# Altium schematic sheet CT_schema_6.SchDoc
size 612 x 325 mm
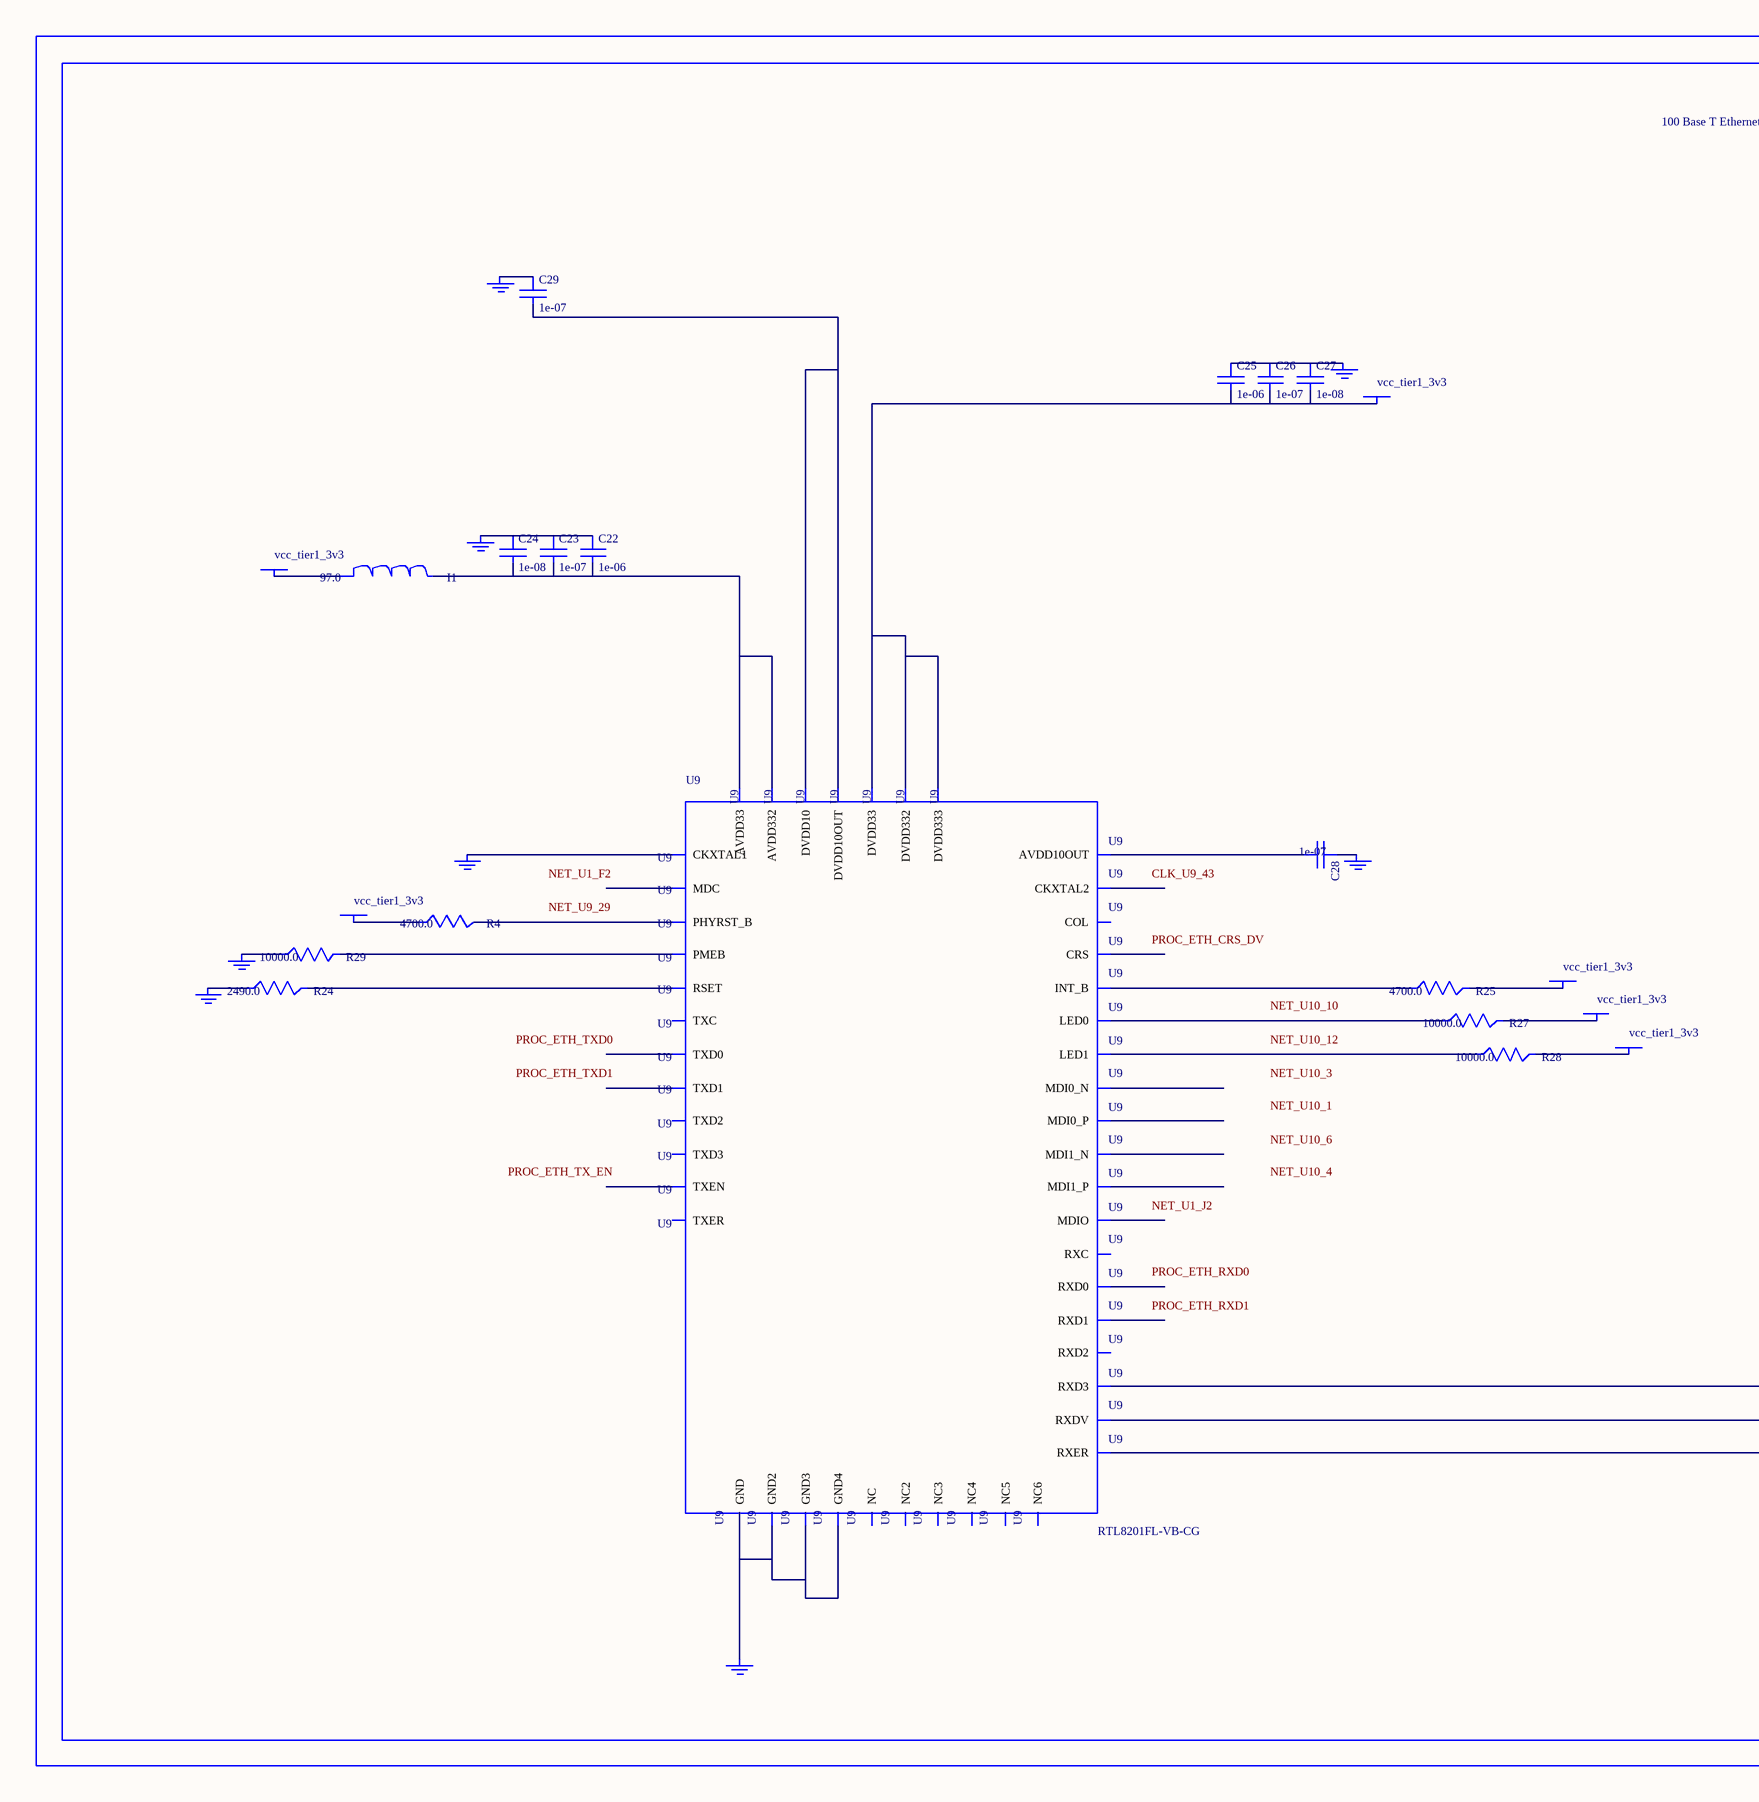
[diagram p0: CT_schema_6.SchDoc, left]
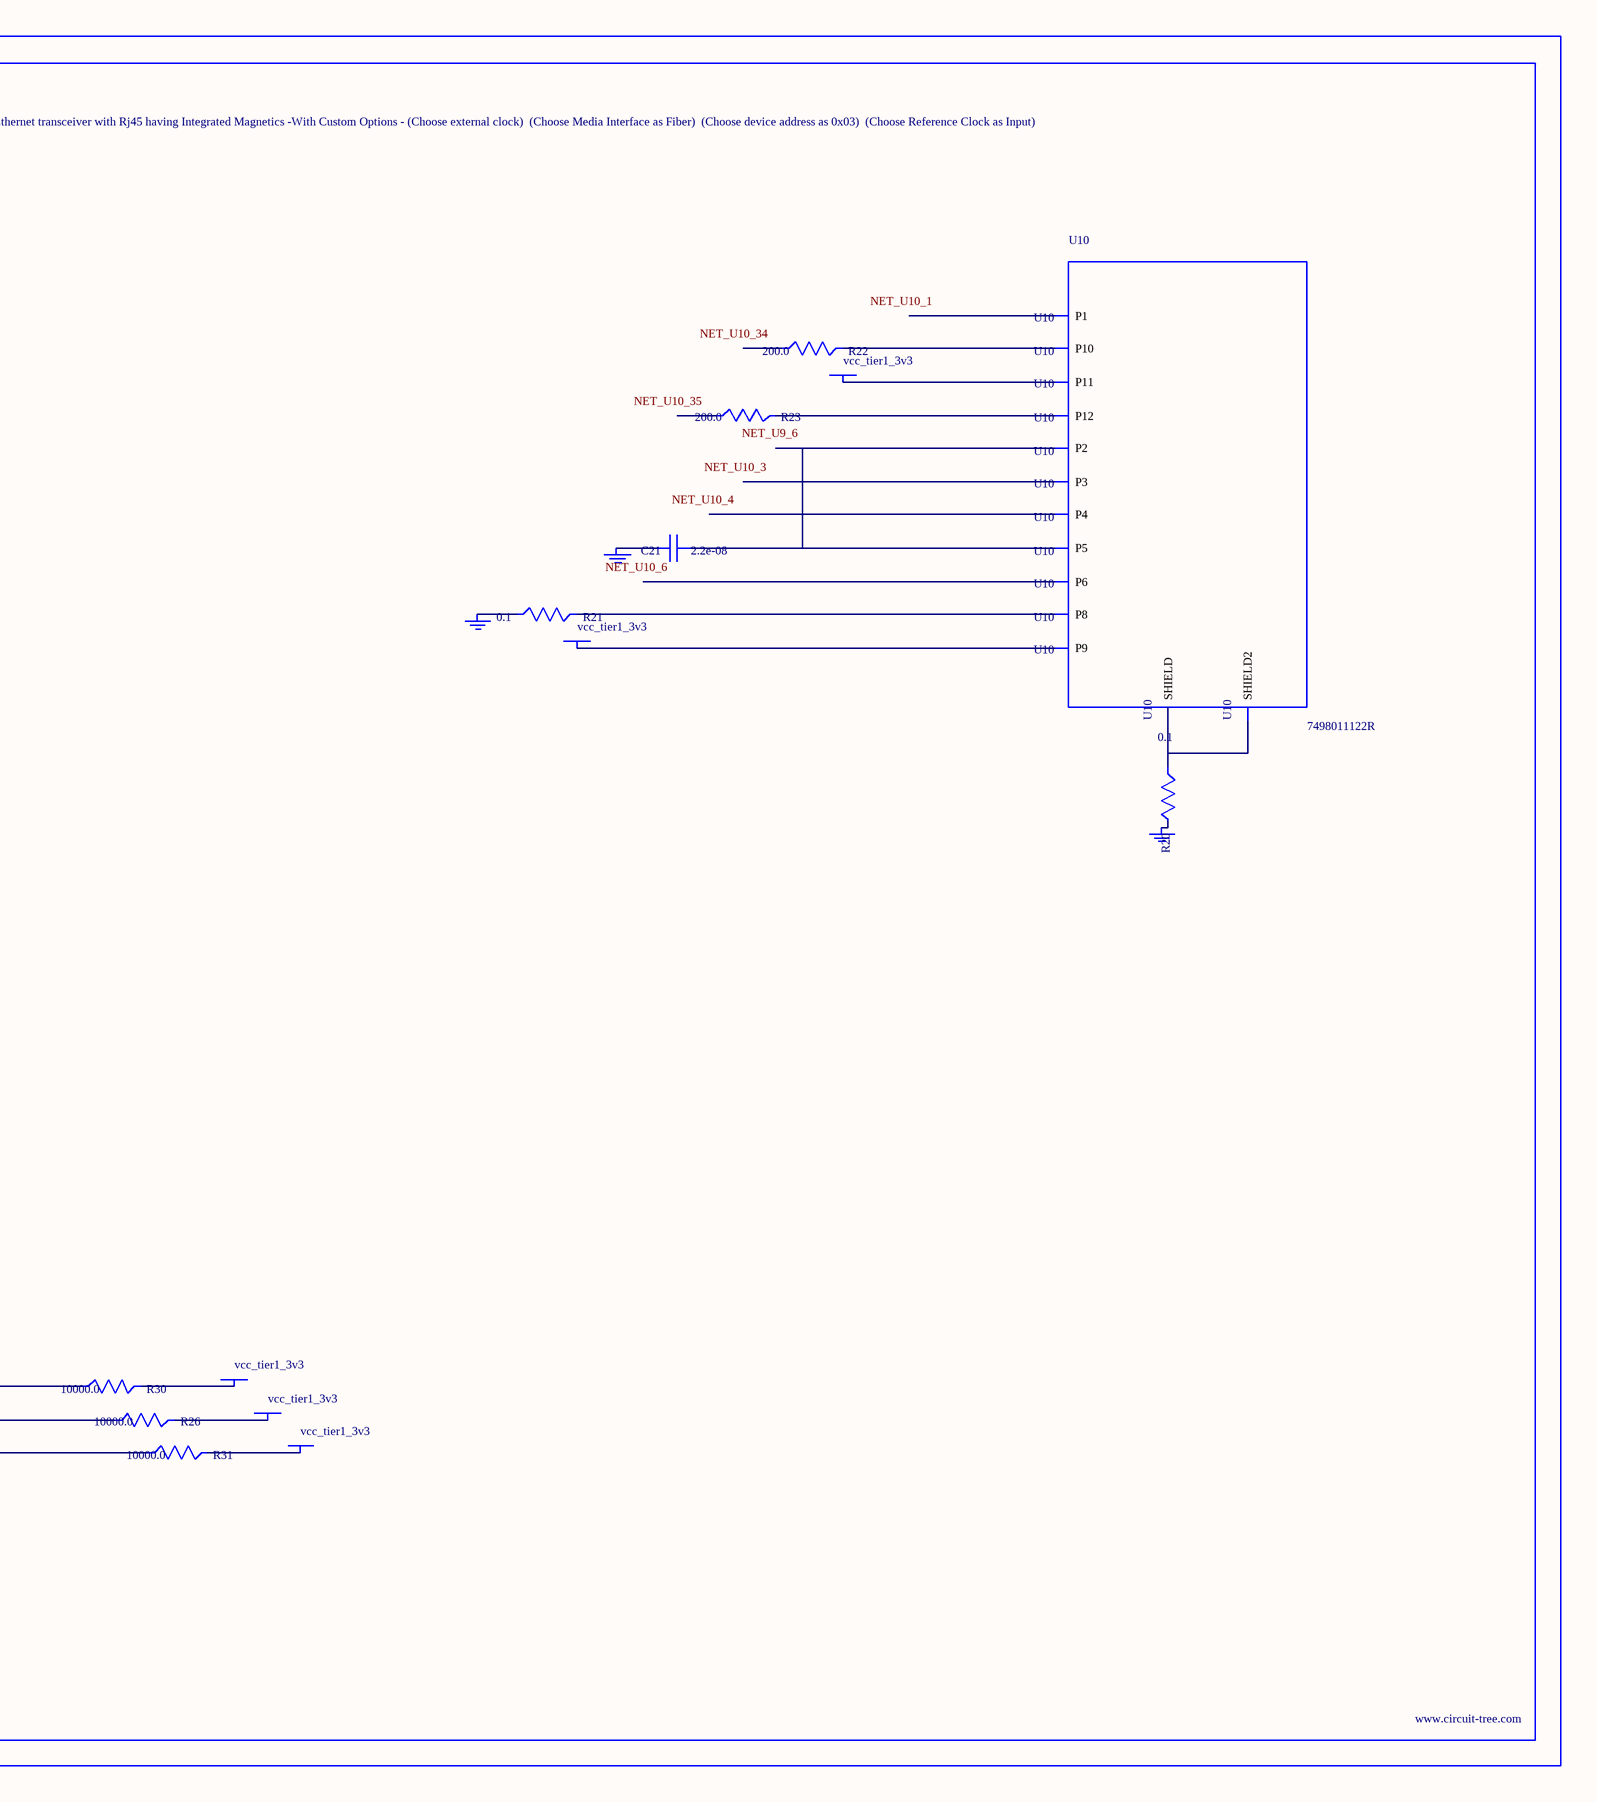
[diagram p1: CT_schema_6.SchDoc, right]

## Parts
BORDER5  (no value)
C21  2.2e-08  [C0402]
C22  1e-06  [C0603]
C23  1e-07  [C0402]
C24  1e-08  [C0402]
C25  1e-06  [C0603]
C26  1e-07  [C0402]
C27  1e-08  [C0402]
C28  1e-07  [C0402]
C29  1e-07  [C0402]
GND_INSTANCE_5_0  (no value)
GND_INSTANCE_5_1  (no value)
GND_INSTANCE_5_2  (no value)
GND_INSTANCE_5_3  (no value)
GND_INSTANCE_5_4  (no value)
GND_INSTANCE_5_5  (no value)
GND_INSTANCE_5_6  (no value)
GND_INSTANCE_5_7  (no value)
GND_INSTANCE_5_8  (no value)
GND_INSTANCE_5_9  (no value)
GND_INSTANCE_5_10  (no value)
I1  97.0  [R0603]
POWER_INSTANCE_5_0  vcc_tier1_3v3
POWER_INSTANCE_5_1  vcc_tier1_3v3
POWER_INSTANCE_5_2  vcc_tier1_3v3
POWER_INSTANCE_5_3  vcc_tier1_3v3
POWER_INSTANCE_5_4  vcc_tier1_3v3
POWER_INSTANCE_5_5  vcc_tier1_3v3
POWER_INSTANCE_5_6  vcc_tier1_3v3
POWER_INSTANCE_5_7  vcc_tier1_3v3
POWER_INSTANCE_5_8  vcc_tier1_3v3
POWER_INSTANCE_5_9  vcc_tier1_3v3
POWER_INSTANCE_5_10  vcc_tier1_3v3
R4  4700.0  [R0603]
R20  0.1  [R0603]
R21  0.1  [R0603]
R22  200.0  [R0603]
R23  200.0  [R0603]
R24  2490.0  [R0603]
R25  4700.0  [R0603]
R26  10000.0  [R0603]
R27  10000.0  [R0603]
R28  10000.0  [R0603]
R29  10000.0  [R0603]
R30  10000.0  [R0603]
R31  10000.0  [R0603]
U9  RTL8201FL-VB-CG  [RTL8201FL-VB-CG]
U10  7498011122R  [7498011122R]

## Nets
NetC21_1: C21.1 U10.2(P2) U10.5(P5)
NetC21_2: C21.2 GND_INSTANCE_5_8.0(GND)
NetC22_1: C22.1 C23.1 C24.1 GND_INSTANCE_5_0.0(GND)
NetC22_2: C22.2 C23.2 C24.2 I1.2 U9.6(AVDD33) U9.41(AVDD332)
NetC25_1: C25.1 C26.1 C27.1 GND_INSTANCE_5_2.0(GND)
NetC25_2: C25.2 C26.2 C27.2 POWER_INSTANCE_5_2.0(PWR) U9.15(DVDD33) U9.21(DVDD332) U9.37(DVDD333)
NetC28_1: C28.1 GND_INSTANCE_5_6.0(GND)
NetC28_2: C28.2 U9.48(AVDD10OUT)
NetC29_1: C29.1 GND_INSTANCE_5_3.0(GND)
NetC29_2: C29.2 U9.28(DVDD10) U9.40(DVDD10OUT)
NetGND_INSTANCE_5_1_0: GND_INSTANCE_5_1.0(GND) R29.1
NetGND_INSTANCE_5_4_0: GND_INSTANCE_5_4.0(GND) U9.42(CKXTAL1)
NetGND_INSTANCE_5_5_0: GND_INSTANCE_5_5.0(GND) R24.1
NetGND_INSTANCE_5_7_0: GND_INSTANCE_5_7.0(GND) U9.7(GND) U9.20(GND2) U9.33(GND3) U9.47(GND4)
NetGND_INSTANCE_5_9_0: GND_INSTANCE_5_9.0(GND) R21.1
NetGND_INSTANCE_5_10_0: GND_INSTANCE_5_10.0(GND) R20.2
NetI1_1: I1.1 POWER_INSTANCE_5_0.0(PWR)
NetPOWER_INSTANCE_5_1_0: POWER_INSTANCE_5_1.0(PWR) R26.2
NetPOWER_INSTANCE_5_3_0: POWER_INSTANCE_5_3.0(PWR) R30.2
NetPOWER_INSTANCE_5_4_0: POWER_INSTANCE_5_4.0(PWR) R25.2
NetPOWER_INSTANCE_5_5_0: POWER_INSTANCE_5_5.0(PWR) R27.2
NetPOWER_INSTANCE_5_6_0: POWER_INSTANCE_5_6.0(PWR) R28.2
NetPOWER_INSTANCE_5_7_0: POWER_INSTANCE_5_7.0(PWR) R31.2
NetPOWER_INSTANCE_5_8_0: POWER_INSTANCE_5_8.0(PWR) R4.1
NetPOWER_INSTANCE_5_9_0: POWER_INSTANCE_5_9.0(PWR) U10.9(P9)
NetPOWER_INSTANCE_5_10_0: POWER_INSTANCE_5_10.0(PWR) U10.11(P11)
NetR4_2: R4.2 U9.29(PHYRST_B)
NetR20_1: R20.1 U10.13(SHIELD) U10.14(SHIELD2)
NetR21_2: R21.2 U10.8(P8)
NetR22_2: R22.2 U10.10(P10)
NetR23_2: R23.2 U10.12(P12)
NetR24_2: R24.2 U9.46(RSET)
NetR25_1: R25.1 U9.32(INT_B)
NetR26_1: R26.1 U9.13(RXDV)
NetR27_1: R27.1 U9.34(LED0)
NetR28_1: R28.1 U9.35(LED1)
NetR29_2: R29.2 U9.10(PMEB)
NetR30_1: R30.1 U9.18(RXD3)
NetR31_1: R31.1 U9.39(RXER)

Not connected (* = marked no-connect by the designer): R22 1; R23 1; U9 1(MDI0_P) 2(MDI0_N) 3(NC) 4(MDI1_P) 5(MDI1_N) 8(NC2) 9(NC3) 11(NC4) 12(TXER) 14(RXD0) 16(RXD1) 17(RXD2) 19(RXC) 22(TXC) 23(TXD0) 24(TXD1) 25(TXD2) 26(TXD3) 27(TXEN) 30(MDC) 31(MDIO) 36(CRS) 38(COL) 43(CKXTAL2) 44(NC5) 45(NC6); U10 1(P1) 3(P3) 4(P4) 6(P6)

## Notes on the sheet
- Labels drawn without touching a wire or pin: CLK_U9_43, NET_U1_F2, NET_U1_J2, NET_U9_6, NET_U9_29, NET_U10_1, NET_U10_3, NET_U10_4, NET_U10_6, NET_U10_10, NET_U10_12, NET_U10_34, NET_U10_35, PROC_ETH_CRS_DV, PROC_ETH_RXD0, PROC_ETH_RXD1, PROC_ETH_TX_EN, PROC_ETH_TXD0, PROC_ETH_TXD1

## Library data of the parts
BORDER5 = BORDER_PAGE5
C21 = C0402C223K3RAC
C22 C25 = C0603C105K3RACTU
C23 C26 C28 C29 = C0402C104K3RACTU
C24 C27 = C0402C103K3RAC
GND_INSTANCE_5_0-GND_INSTANCE_5_10 = GND
I1 = I1
POWER_INSTANCE_5_0-POWER_INSTANCE_5_10 = PWR
R4 R25 = RC0603JR-074K7L
R20 R21 = ERJ-3RSFR10V
R22 R23 = RC0603JR-07200RL
R24 = ERA-3AED2490V
R26-R31 = RC0603JR-0710KL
